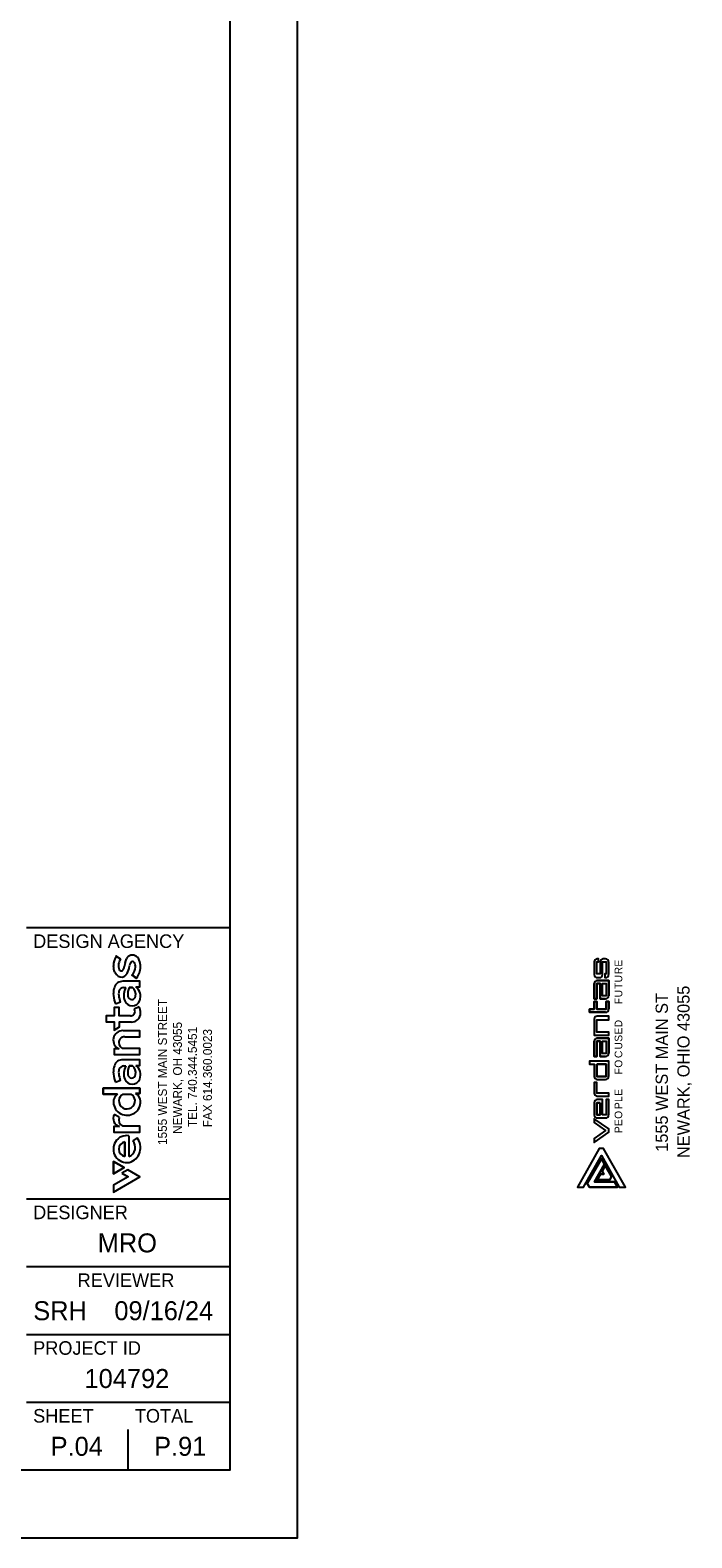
# Model space of a CAD drawing. Extents: x 0 to 36.9, y 0 to 22.
# Drawn here: x 32.03 to 36.91, y 0 to 11.12 of the extents above; entities that cross this region are included whole.
import ezdxf

# ---------------------------------------------------------------- set-up
doc = ezdxf.new("R2010")
doc.units = 0
for name, color, linetype in [('CS-ANNO-TTLB-LOGO', 7, 'Continuous'), ('Default', 7, 'Continuous'), ('SH_Border', 7, 'Continuous'), ('SH_Cut_Line', 7, 'Continuous'), ('SH_Data', 7, 'Continuous'), ('SH_Text', 7, 'Continuous')]:
    doc.layers.add(name, color=color, linetype=linetype)

msp = doc.modelspace()

# ---------------------------------------------------------------- linework, layer by layer
at = {"layer": 'CS-ANNO-TTLB-LOGO'}
for p, q in [((36.187, 4.247), (36.187, 4.154)), ((36.218, 4.27), (36.209, 4.27)), ((36.271, 4.27), (36.254, 4.27)), ((36.294, 4.154), (36.294, 4.247)), ((36.209, 4.132), (36.226, 4.132)), ((36.187, 3.974), (36.187, 4.087)), ((36.187, 3.55), (36.187, 3.662)), ((36.209, 3.381), (36.271, 3.381)), ((36.294, 3.119), (36.294, 3.232)), ((36.187, 3.209), (36.187, 3.119)), ((36.209, 3.097), (36.271, 3.097))]:
    msp.add_line(p, q, dxfattribs=at)
for points in [[(36.232, 4.247), (36.232, 4.16), (36.206, 4.16), (36.206, 4.247), (36.218, 4.247), (36.218, 4.27)], [(36.249, 4.154), (36.249, 4.247), (36.274, 4.247), (36.274, 4.16), (36.266, 4.16), (36.266, 4.132), (36.271, 4.132)], [(36.271, 3.974), (36.232, 3.974), (36.232, 4.087), (36.206, 4.087), (36.206, 3.974), (36.187, 3.974)], [(36.209, 4.109), (36.294, 4.109), (36.294, 3.997)], [(36.152, 3.898), (36.187, 3.898), (36.187, 3.955), (36.206, 3.955), (36.206, 3.898), (36.274, 3.898), (36.274, 3.955), (36.294, 3.955), (36.294, 3.898)], [(36.271, 3.876), (36.152, 3.876), (36.152, 3.898)], [(36.187, 3.825), (36.187, 3.707), (36.294, 3.707), (36.294, 3.73), (36.206, 3.73), (36.206, 3.82), (36.294, 3.82)], [(36.294, 3.82), (36.294, 3.848), (36.209, 3.848)], [(36.209, 3.685), (36.294, 3.685), (36.294, 3.572)], [(36.271, 3.55), (36.232, 3.55), (36.232, 3.662), (36.206, 3.662), (36.206, 3.55), (36.187, 3.55)], [(36.152, 3.516), (36.152, 3.493), (36.187, 3.493), (36.187, 3.403)], [(36.294, 3.403), (36.294, 3.516), (36.152, 3.516)], [(36.294, 3.28), (36.206, 3.28), (36.206, 3.358), (36.187, 3.358), (36.187, 3.28)], [(36.209, 3.257), (36.294, 3.257), (36.294, 3.28)], [(36.294, 3.232), (36.274, 3.232), (36.274, 3.119), (36.249, 3.119), (36.249, 3.232), (36.209, 3.232)]]:
    msp.add_lwpolyline(points, dxfattribs=at)
for points in [[(36.249, 4.087), (36.274, 4.087), (36.274, 3.997), (36.249, 3.997)], [(36.249, 3.662), (36.274, 3.662), (36.274, 3.572), (36.249, 3.572)], [(36.206, 3.493), (36.206, 3.403), (36.274, 3.403), (36.274, 3.493)], [(36.232, 3.209), (36.206, 3.209), (36.206, 3.119), (36.232, 3.119)], [(36.271, 3.003), (36.187, 2.944), (36.187, 2.916), (36.294, 2.991), (36.294, 3.015), (36.187, 3.089), (36.187, 3.062)]]:
    msp.add_lwpolyline(points, close=True, dxfattribs=at)
for centre, start, end in [((36.209, 4.247), 90, 180), ((36.254, 4.247), 90, 180), ((36.271, 4.247), 360, 90), ((36.209, 4.154), 180, 270), ((36.226, 4.154), 270, 0), ((36.271, 4.154), 270, 0), ((36.209, 4.087), 90, 180), ((36.271, 3.997), 270, 360), ((36.271, 3.898), 270, 360), ((36.209, 3.825), 90, 180), ((36.209, 3.662), 90, 180), ((36.271, 3.572), 270, 360), ((36.209, 3.403), 180, 270), ((36.271, 3.403), 270, 0), ((36.209, 3.28), 180, 270), ((36.209, 3.209), 90, 180), ((36.209, 3.119), 180, 270), ((36.271, 3.119), 270, 0)]:
    msp.add_arc(centre, 0.0225, start, end, dxfattribs=at)
at = {"layer": 'Default'}
for p, q in [((36.187, 4.247), (36.187, 4.154)), ((36.271, 4.27), (36.254, 4.27)), ((36.294, 4.154), (36.294, 4.247)), ((36.209, 4.132), (36.226, 4.132)), ((36.209, 3.381), (36.271, 3.381)), ((36.187, 3.209), (36.187, 3.119)), ((36.209, 3.097), (36.271, 3.097)), ((36.136, 2.613), (36.24, 2.796)), ((36.24, 2.796), (36.262, 2.756)), ((36.262, 2.756), (36.188, 2.625)), ((36.152, 2.585), (36.136, 2.613)), ((36.359, 2.585), (36.152, 2.585)), ((36.188, 2.625), (36.336, 2.625)), ((36.336, 2.625), (36.359, 2.585))]:
    msp.add_line(p, q, dxfattribs=at)
for points in [[(36.232, 4.247), (36.232, 4.16), (36.206, 4.16), (36.206, 4.247), (36.218, 4.247), (36.218, 4.27), (36.209, 4.27)], [(36.249, 4.154), (36.249, 4.247), (36.274, 4.247), (36.274, 4.16), (36.266, 4.16), (36.266, 4.132), (36.271, 4.132)], [(36.187, 4.087), (36.187, 3.974), (36.206, 3.974), (36.206, 4.087), (36.232, 4.087), (36.232, 3.974), (36.271, 3.974)], [(36.294, 3.997), (36.294, 4.109), (36.209, 4.109)], [(36.294, 3.898), (36.294, 3.955), (36.274, 3.955), (36.274, 3.898), (36.206, 3.898), (36.206, 3.955), (36.187, 3.955), (36.187, 3.898), (36.152, 3.898), (36.152, 3.876), (36.271, 3.876)], [(36.187, 3.825), (36.187, 3.707), (36.294, 3.707), (36.294, 3.73), (36.206, 3.73), (36.206, 3.82), (36.294, 3.82), (36.294, 3.848), (36.209, 3.848)], [(36.294, 3.572), (36.294, 3.685), (36.209, 3.685)], [(36.187, 3.662), (36.187, 3.55), (36.206, 3.55), (36.206, 3.662), (36.232, 3.662), (36.232, 3.55), (36.271, 3.55)], [(36.294, 3.403), (36.294, 3.516), (36.152, 3.516), (36.152, 3.493), (36.187, 3.493), (36.187, 3.403)], [(36.209, 3.257), (36.294, 3.257), (36.294, 3.28), (36.206, 3.28), (36.206, 3.358), (36.187, 3.358), (36.187, 3.28)], [(36.294, 3.119), (36.294, 3.232), (36.274, 3.232), (36.274, 3.119), (36.249, 3.119), (36.249, 3.232), (36.209, 3.232)]]:
    msp.add_lwpolyline(points, dxfattribs=at)
for points in [[(36.274, 4.087), (36.274, 3.997), (36.249, 3.997), (36.249, 4.087)], [(36.274, 3.662), (36.274, 3.572), (36.249, 3.572), (36.249, 3.662)], [(36.206, 3.493), (36.274, 3.493), (36.274, 3.403), (36.206, 3.403)], [(36.232, 3.209), (36.232, 3.119), (36.206, 3.119), (36.206, 3.209)], [(36.187, 2.944), (36.187, 2.916), (36.294, 2.991), (36.294, 3.015), (36.187, 3.089), (36.187, 3.062), (36.271, 3.003)], [(36.24, 2.819), (36.371, 2.585), (36.417, 2.585), (36.256, 2.871), (36.223, 2.871), (36.063, 2.585), (36.108, 2.585)], [(36.108, 2.585), (36.24, 2.819), (36.371, 2.585), (36.417, 2.585), (36.256, 2.871), (36.223, 2.871), (36.063, 2.585)], [(36.136, 2.613), (36.152, 2.585), (36.359, 2.585), (36.336, 2.625), (36.188, 2.625), (36.262, 2.756), (36.24, 2.796)], [(36.233, 2.681), (36.21, 2.641), (36.301, 2.641), (36.314, 2.664), (36.269, 2.745), (36.246, 2.705), (36.259, 2.681)], [(36.233, 2.681), (36.259, 2.681), (36.246, 2.705), (36.269, 2.745), (36.314, 2.664), (36.301, 2.641), (36.21, 2.641)]]:
    msp.add_lwpolyline(points, close=True, dxfattribs=at)
for centre, start, end in [((36.209, 4.247), 90, 180), ((36.254, 4.247), 90, 180), ((36.271, 4.247), 360, 90), ((36.209, 4.154), 180, 270), ((36.226, 4.154), 270, 0), ((36.271, 4.154), 270, 0), ((36.209, 4.087), 90, 180), ((36.271, 3.997), 270, 0), ((36.271, 3.898), 270, 0), ((36.209, 3.825), 90, 180), ((36.209, 3.662), 90, 180), ((36.271, 3.572), 270, 0), ((36.209, 3.403), 180, 270), ((36.271, 3.403), 270, 0), ((36.209, 3.28), 180, 270), ((36.209, 3.209), 90, 180), ((36.209, 3.119), 180, 270), ((36.271, 3.119), 270, 0)]:
    msp.add_arc(centre, 0.0225, start, end, dxfattribs=at)
at = {"layer": 'SH_Border'}
for p, q in [((32, 4.5), (33.5, 4.5)), ((32, 2.5), (33.5, 2.5)), ((32, 2), (33.5, 2)), ((32, 1.5), (33.5, 1.5)), ((32, 1), (33.5, 1))]:
    msp.add_line(p, q, dxfattribs=at)
msp.add_lwpolyline([(1.5, 21.5), (33.5, 21.5), (33.5, 0.5), (1.5, 0.5)], close=True, dxfattribs=at)
at = {"layer": 'SH_Cut_Line'}
msp.add_lwpolyline([(0, 0), (34, 0), (34, 22), (0, 22)], close=True, dxfattribs=at)
at = {"layer": 'SH_Data'}
for p, q in [((32.75, 3.5), (32.75, 3.5)), ((32.75, 0.5), (32.75, 0.8)), ((32.375, 0.675), (32.375, 0.675))]:
    msp.add_line(p, q, dxfattribs=at)
at = {"layer": 'SH_Text'}
for p, q in [((32.694, 4.267), (32.663, 4.29)), ((32.728, 4.241), (32.721, 4.21)), ((32.757, 4.199), (32.761, 4.219)), ((32.78, 4.151), (32.812, 4.127)), ((32.717, 4.059), (32.733, 4.059)), ((32.759, 4.059), (32.782, 4.059)), ((32.653, 3.951), (32.658, 3.939)), ((32.831, 3.915), (32.796, 3.899)), ((32.717, 3.48), (32.733, 3.48)), ((32.759, 3.48), (32.782, 3.48)), ((32.653, 3.372), (32.658, 3.36)), ((32.712, 3.272), (32.772, 3.272)), ((32.684, 3.101), (32.647, 3.123)), ((32.726, 2.92), (32.726, 2.813)), ((32.757, 2.812), (32.757, 2.965)), ((32.816, 2.95), (32.784, 2.928))]:
    msp.add_line(p, q, dxfattribs=at)
for points in [[(32.695, 4.269), (32.663, 4.292), (32.663, 4.29)], [(32.694, 4.267), (32.695, 4.269)], [(32.728, 4.241), (32.721, 4.21)], [(32.757, 4.199), (32.761, 4.219)], [(32.78, 4.151), (32.777, 4.149), (32.809, 4.124), (32.812, 4.127)], [(32.807, 4.063), (32.837, 4.063), (32.837, 4.104), (32.712, 4.104)], [(32.807, 4.063), (32.837, 4.063), (32.837, 4.104), (32.712, 4.104)], [(32.717, 4.059), (32.733, 4.059)], [(32.782, 4.059), (32.759, 4.059)], [(32.767, 3.849), (32.685, 3.849), (32.685, 3.91), (32.647, 3.91), (32.647, 3.849), (32.588, 3.849), (32.588, 3.804), (32.647, 3.804), (32.647, 3.744), (32.686, 3.768), (32.686, 3.804), (32.775, 3.804)], [(32.767, 3.849), (32.685, 3.849), (32.685, 3.91), (32.647, 3.91), (32.647, 3.849), (32.588, 3.849), (32.588, 3.804), (32.647, 3.804), (32.647, 3.744), (32.686, 3.768), (32.686, 3.804), (32.775, 3.804)], [(32.653, 3.951), (32.658, 3.939)], [(32.658, 3.939), (32.694, 3.953), (32.69, 3.963)], [(32.658, 3.939), (32.694, 3.953), (32.69, 3.963)], [(32.831, 3.915), (32.796, 3.899)], [(32.725, 3.695), (32.837, 3.695), (32.837, 3.74), (32.713, 3.74)], [(32.725, 3.695), (32.837, 3.695), (32.837, 3.74), (32.713, 3.74)], [(32.684, 3.606), (32.647, 3.606), (32.647, 3.564), (32.837, 3.564), (32.837, 3.609), (32.71, 3.609)], [(32.684, 3.606), (32.647, 3.606), (32.647, 3.564), (32.837, 3.564), (32.837, 3.609), (32.71, 3.609)], [(32.807, 3.484), (32.837, 3.484), (32.837, 3.526), (32.712, 3.526)], [(32.807, 3.484), (32.837, 3.484), (32.837, 3.526), (32.712, 3.526)], [(32.717, 3.48), (32.733, 3.48)], [(32.782, 3.48), (32.759, 3.48)], [(32.653, 3.372), (32.658, 3.36)], [(32.658, 3.36), (32.694, 3.375), (32.69, 3.384)], [(32.658, 3.36), (32.694, 3.375), (32.69, 3.384)], [(32.673, 3.272), (32.566, 3.272), (32.566, 3.317), (32.837, 3.317), (32.837, 3.276), (32.804, 3.276)], [(32.804, 3.276), (32.837, 3.276), (32.837, 3.317), (32.566, 3.317), (32.566, 3.272), (32.673, 3.272)], [(32.712, 3.272), (32.772, 3.272)], [(32.684, 3.101), (32.647, 3.123)], [(32.687, 3.033), (32.646, 3.033), (32.646, 2.992), (32.837, 2.992), (32.837, 3.036), (32.711, 3.036)], [(32.687, 3.033), (32.646, 3.033), (32.646, 2.992), (32.837, 2.992), (32.837, 3.036), (32.711, 3.036)], [(32.726, 2.813), (32.726, 2.92)], [(32.757, 2.812), (32.757, 2.965)], [(32.816, 2.95), (32.784, 2.928)], [(32.642, 2.775), (32.642, 2.684), (32.72, 2.73), (32.642, 2.775)], [(32.705, 2.688), (32.75, 2.662), (32.642, 2.6), (32.642, 2.55), (32.837, 2.662), (32.749, 2.713), (32.705, 2.688)]]:
    msp.add_lwpolyline(points, dxfattribs=at)
for points in [[(32.72, 2.73), (32.642, 2.684), (32.642, 2.775)], [(32.705, 2.688), (32.75, 2.662), (32.642, 2.6), (32.642, 2.55), (32.837, 2.662), (32.749, 2.713)]]:
    msp.add_lwpolyline(points, close=True, dxfattribs=at)
for centre, radius, start, end in [((32.773, 4.219), 0.131, 147.2233, 179.842), ((32.773, 4.219), 0.131, 147.2233, 179.842), ((32.774, 4.217), 0.0948, 148.1233, 178.1135), ((32.774, 4.217), 0.0948, 148.1233, 178.1135), ((32.854, 4.212), 0.13, 154.0447, 167.2149), ((32.854, 4.212), 0.13, 154.0447, 167.2149), ((32.782, 4.248), 0.0493, 52.7092, 154.2166), ((32.782, 4.248), 0.0493, 52.7092, 154.2166), ((32.855, 4.204), 0.0949, 158.1863, 170.6328), ((32.855, 4.204), 0.0949, 158.1863, 170.6328), ((32.783, 4.234), 0.0165, 26.9165, 163.602), ((32.783, 4.234), 0.0165, 26.9165, 163.602), ((32.739, 4.213), 0.0655, 357.0077, 26.3112), ((32.739, 4.213), 0.0655, 357.0077, 26.3112), ((32.767, 4.232), 0.0711, 22.8278, 50.7157), ((32.767, 4.232), 0.0711, 22.8278, 50.7157), ((32.722, 4.213), 0.12, 359.0192, 22.9257), ((32.722, 4.213), 0.12, 359.0192, 22.9257), ((32.755, 4.218), 0.114, 179.0109, 203.56), ((32.755, 4.218), 0.114, 179.0109, 203.56), ((32.713, 4.199), 0.067, 203.3692, 237.807), ((32.713, 4.199), 0.067, 203.3692, 237.807), ((32.701, 4.181), 0.0458, 238.9453, 317.6829), ((32.701, 4.181), 0.0458, 238.9453, 317.6829), ((32.749, 4.219), 0.0702, 179.0539, 195.6921), ((32.749, 4.219), 0.0702, 179.0539, 195.6921), ((32.714, 4.208), 0.0335, 193.8561, 223.7191), ((32.714, 4.208), 0.0335, 193.8561, 223.7191), ((32.701, 4.195), 0.0148, 224.7822, 330.4366), ((32.701, 4.195), 0.0148, 224.7822, 330.4366), ((32.641, 4.225), 0.0819, 332.9002, 349.3831), ((32.641, 4.225), 0.0819, 332.9002, 349.3831), ((32.654, 4.218), 0.105, 320.1259, 349.7023), ((32.654, 4.218), 0.105, 320.1259, 349.7023), ((32.711, 4.214), 0.0932, 317.363, 356.9244), ((32.711, 4.214), 0.0932, 317.363, 356.9244), ((32.713, 4.21), 0.129, 320.5166, 0.4341), ((32.713, 4.21), 0.129, 320.5166, 0.4341), ((32.77, 4.017), 0.128, 160.8128, 180.9317), ((32.77, 4.017), 0.128, 160.8128, 180.9317), ((32.84, 4.018), 0.199, 180.9467, 199.8354), ((32.84, 4.018), 0.199, 180.9467, 199.8354), ((32.71, 4.04), 0.0639, 88.076, 162.8642), ((32.71, 4.04), 0.0639, 88.076, 162.8642), ((32.745, 4.012), 0.0647, 163.2522, 179.9971), ((32.745, 4.012), 0.0647, 163.2522, 179.9971), ((32.832, 4.017), 0.152, 181.6616, 200.8714), ((32.832, 4.017), 0.152, 181.6616, 200.8714), ((32.719, 4.021), 0.0374, 92.9671, 165.223), ((32.719, 4.021), 0.0374, 92.9671, 165.223), ((32.826, 4.002), 0.108, 148.3497, 202.4708), ((32.826, 4.002), 0.108, 148.3497, 202.4708), ((32.853, 4.012), 0.105, 153.8372, 188.8746), ((32.853, 4.012), 0.105, 153.8372, 188.8746), ((32.743, 4.008), 0.0637, 348.1247, 52.3678), ((32.743, 4.008), 0.0637, 348.1247, 52.3678), ((32.756, 3.993), 0.0857, 338.2774, 53.7949), ((32.756, 3.993), 0.0857, 338.2774, 53.7949), ((32.78, 3.982), 0.0592, 201.6764, 339.7268), ((32.78, 3.982), 0.0592, 201.6764, 339.7268), ((32.777, 3.997), 0.0281, 182.327, 355.3778), ((32.777, 3.997), 0.0281, 182.327, 355.3778), ((32.758, 3.877), 0.0432, 1.8638, 29.9651), ((32.758, 3.877), 0.0432, 1.8638, 29.9651), ((32.748, 3.871), 0.0939, 359.5424, 28.2495), ((32.748, 3.871), 0.0939, 359.5424, 28.2495), ((32.77, 3.881), 0.0314, 265.0692, 356.3548), ((32.77, 3.881), 0.0314, 265.0692, 356.3548), ((32.778, 3.868), 0.0642, 267.8641, 1.6213), ((32.778, 3.868), 0.0642, 267.8641, 1.6213), ((32.711, 3.67), 0.0703, 88.9896, 246.9111), ((32.711, 3.67), 0.0703, 88.9896, 246.9111), ((32.726, 3.654), 0.0434, 137.3049, 182.9688), ((32.726, 3.654), 0.0434, 137.3049, 182.9688), ((32.723, 3.652), 0.0433, 86.9739, 132.7421), ((32.723, 3.652), 0.0433, 86.9739, 132.7421), ((32.73, 3.652), 0.0477, 180.3466, 244.9113), ((32.73, 3.652), 0.0477, 180.3466, 244.9113), ((32.77, 3.438), 0.128, 160.8128, 180.9317), ((32.77, 3.438), 0.128, 160.8128, 180.9317), ((32.71, 3.462), 0.0639, 88.076, 162.8642), ((32.71, 3.462), 0.0639, 88.076, 162.8642), ((32.745, 3.434), 0.0647, 163.2522, 179.9971), ((32.745, 3.434), 0.0647, 163.2522, 179.9971), ((32.719, 3.443), 0.0374, 92.9671, 165.223), ((32.719, 3.443), 0.0374, 92.9671, 165.223), ((32.826, 3.423), 0.108, 148.3497, 202.4708), ((32.826, 3.423), 0.108, 148.3497, 202.4708), ((32.853, 3.434), 0.105, 153.8372, 188.8746), ((32.853, 3.434), 0.105, 153.8372, 188.8746), ((32.743, 3.43), 0.0637, 348.1247, 52.3678), ((32.743, 3.43), 0.0637, 348.1247, 52.3678), ((32.756, 3.415), 0.0857, 338.2774, 53.7949), ((32.756, 3.415), 0.0857, 338.2774, 53.7949), ((32.84, 3.44), 0.199, 180.9467, 199.8354), ((32.84, 3.44), 0.199, 180.9467, 199.8354), ((32.832, 3.438), 0.152, 181.6616, 200.8714), ((32.832, 3.438), 0.152, 181.6616, 200.8714), ((32.78, 3.404), 0.0592, 201.6764, 339.7268), ((32.78, 3.404), 0.0592, 201.6764, 339.7268), ((32.777, 3.419), 0.0281, 182.327, 355.3778), ((32.777, 3.419), 0.0281, 182.327, 355.3778), ((32.713, 3.213), 0.0714, 124.2843, 181.2723), ((32.713, 3.213), 0.0714, 124.2843, 181.2723), ((32.741, 3.221), 0.0586, 119.9007, 175.5797), ((32.741, 3.221), 0.0586, 119.9007, 175.5797), ((32.742, 3.222), 0.0595, 176.4529, 5.055), ((32.742, 3.222), 0.0595, 176.4529, 5.055), ((32.743, 3.221), 0.0588, 6.0666, 60.041), ((32.743, 3.221), 0.0588, 6.0666, 60.041), ((32.775, 3.215), 0.0671, 5.3084, 64.5252), ((32.775, 3.215), 0.0671, 5.3084, 64.5252), ((32.703, 3.094), 0.0628, 152.6524, 255.2929), ((32.703, 3.094), 0.0628, 152.6524, 255.2929), ((32.742, 3.216), 0.1, 182.7719, 2.9779), ((32.742, 3.216), 0.1, 182.7719, 2.9779), ((32.736, 3.084), 0.0545, 162.1384, 242.0408), ((32.736, 3.084), 0.0545, 162.1384, 242.0408), ((32.741, 2.867), 0.0996, 81.0446, 280.2577), ((32.741, 2.867), 0.0996, 81.0446, 280.2577), ((32.735, 2.866), 0.0543, 98.8378, 261.1622), ((32.735, 2.866), 0.0543, 98.8378, 261.1622), ((32.731, 2.879), 0.072, 290.9232, 42.7391), ((32.731, 2.879), 0.072, 290.9232, 42.7391), ((32.728, 2.878), 0.114, 285.6668, 39.3699), ((32.728, 2.878), 0.114, 285.6668, 39.3699)]:
    msp.add_arc(centre, radius, start, end, dxfattribs=at)

# ---------------------------------------------------------------- texts
at = {"layer": 'Default'}
for s, p in [('E', (36.394, 4.212)), ('R', (36.394, 4.156)), ('U', (36.394, 4.096)), ('T', (36.394, 4.047)), ('U', (36.394, 3.986)), ('F', (36.394, 3.935)), ('D', (36.394, 3.765)), ('S', (36.394, 3.659)), ('E', (36.394, 3.712)), ('C', (36.394, 3.538)), ('U', (36.394, 3.601)), ('O', (36.394, 3.467)), ('F', (36.394, 3.418)), ('E', (36.394, 3.26)), ('L', (36.394, 3.214)), ('O', (36.394, 3.09)), ('P', (36.394, 3.162)), ('E', (36.394, 3.037)), ('P', (36.394, 2.985))]:
    msp.add_text(s, height=0.0563, rotation=90, dxfattribs=at).set_placement(p)
at = {"layer": 'SH_Data'}
for s, height, p in [('DESIGN AGENCY', 0.1, (32.05, 4.35)), ('DESIGNER', 0.1, (32.05, 2.35)), ('MRO', 0.14, (32.526, 2.105)), ('REVIEWER', 0.1, (32.378, 1.85)), ('SRH', 0.14, (32.051, 1.605)), ('09/16/24', 0.14, (32.649, 1.605)), ('PROJECT ID', 0.1, (32.05, 1.35)), ('104792', 0.14, (32.429, 1.105)), ('SHEET', 0.1, (32.05, 0.85)), ('TOTAL', 0.1, (32.8, 0.85)), ('P.04', 0.14, (32.179, 0.605)), ('P.91', 0.14, (32.942, 0.605))]:
    msp.add_text(s, height=height, dxfattribs=at).set_placement(p)
at = {"layer": 'SH_Text'}
for s, height, p in [('1555 WEST MAIN ST', 0.09, (36.73, 2.847)), ('NEWARK, OHIO 43055', 0.09, (36.89, 2.801)), ('1555 WEST MAIN STREET', 0.06497, (33.036, 2.897)), ('NEWARK, OH 43055', 0.06497, (33.147, 2.979)), ('TEL. 740.344.5451', 0.06497, (33.257, 3.029)), ('FAX 614.360.0023', 0.06497, (33.368, 3.028))]:
    msp.add_text(s, height=height, rotation=90, dxfattribs=at).set_placement(p)

doc.saveas('drawing.dxf')
